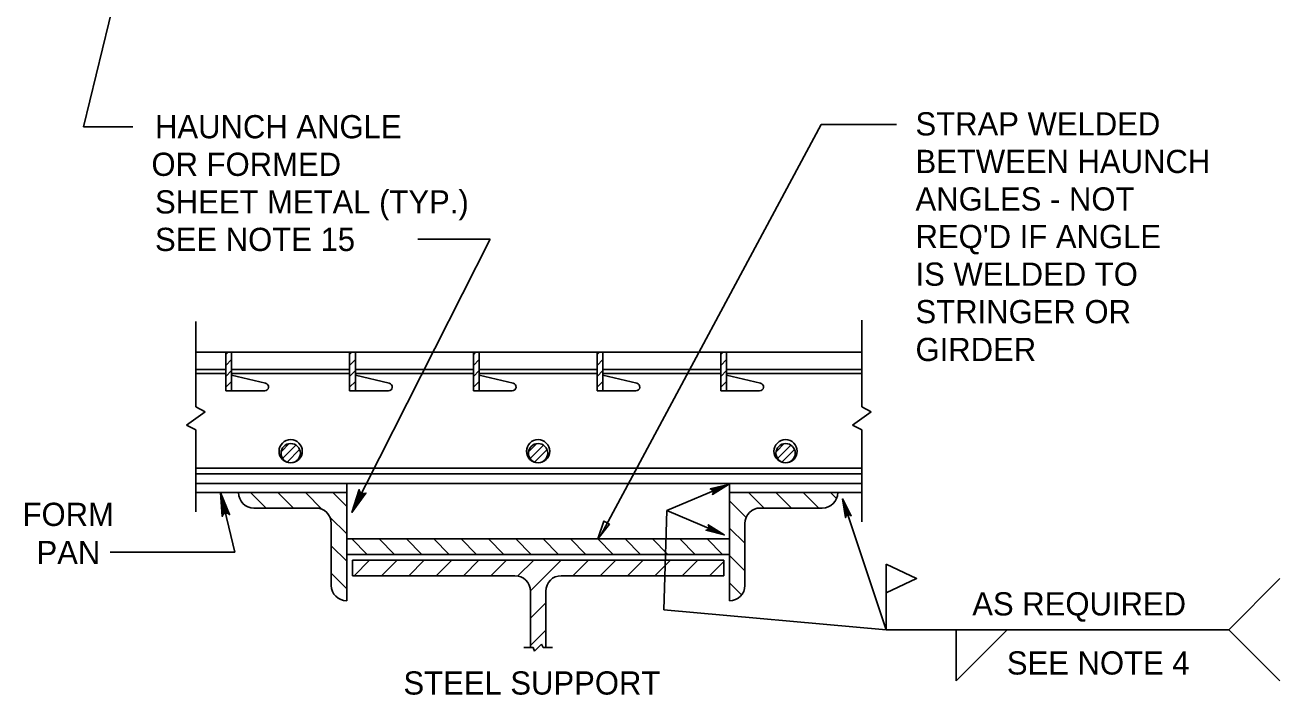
# Model space of a CAD drawing. Extents: x -24512 to -22484, y 4569 to 6351.
# Drawn here: x -23765 to -23602.7, y 5363.7 to 5450.3 of the extents above; entities that cross this region are included whole.
import ezdxf

# ---------------------------------------------------------------- set-up
doc = ezdxf.new("R2010")
doc.units = 0
for name, color, linetype in [('1', 7, 'Continuous'), ('10', 7, 'Continuous'), ('3', 7, 'Continuous'), ('4', 7, 'Continuous'), ('9', 7, 'Continuous')]:
    doc.layers.add(name, color=color, linetype=linetype)

# ---------------------------------------------------------------- blocks, each defined once
blk = doc.blocks.new('SYM012')
at = {"layer": '3'}
for p, q in [((12.764875, 6.492125), (12.825, 6.552375)), ((12.764875, 6.207), (12.916, 6.35825)), ((12.764875, 5.921875), (12.916, 6.073125)), ((12.764875, 5.63675), (12.916, 5.788))]:
    blk.add_line(p, q, dxfattribs=at)
blk = doc.blocks.new('SYM013')
at = {"layer": '3'}
for p, q in [((10.418625, 11.48775), (10.630375, 11.699625)), ((10.457, 11.312375), (10.805875, 11.66125)), ((10.574625, 11.21625), (10.902, 11.5435)), ((10.82875, 11.256375), (10.86175, 11.2895))]:
    blk.add_line(p, q, dxfattribs=at)
blk = doc.blocks.new('SYM022')
at = {"layer": '3'}
for p, q in [((104.738375, 112.667875), (104.335125, 113.071125)), ((105.451125, 112.667875), (105.048, 113.071125)), ((106.199875, 112.632), (105.76075, 113.071125)), ((106.84, 112.70475), (106.473625, 113.071125)), ((106.84, 111.991875), (106.400875, 112.431)), ((106.84, 111.279125), (106.43675, 111.68225)), ((106.84, 110.56625), (106.43675, 110.9695))]:
    blk.add_line(p, q, dxfattribs=at)
blk = doc.blocks.new('SYM023')
at = {"layer": '3'}
for p, q in [((117.103, 112.421), (116.66825, 112.85575)), ((117.568875, 112.667875), (117.16575, 113.071125)), ((118.28175, 112.667875), (117.8785, 113.071125)), ((118.9945, 112.667875), (118.591375, 113.071125)), ((119.459625, 112.915625), (119.304125, 113.071125)), ((117.0715, 111.739625), (116.66825, 112.142875)), ((117.0715, 111.026875), (116.66825, 111.430125)), ((116.98425, 110.401375), (116.66825, 110.71725))]:
    blk.add_line(p, q, dxfattribs=at)
blk = doc.blocks.new('SYM024')
at = {"layer": '3'}
for p, q in [((107.372375, 111.4595), (106.969125, 111.86275)), ((108.08525, 111.4595), (107.682, 111.86275)), ((108.798, 111.4595), (108.39475, 111.86275)), ((109.51075, 111.4595), (109.107625, 111.86275)), ((110.223625, 111.4595), (109.820375, 111.86275)), ((110.936375, 111.4595), (110.53325, 111.86275)), ((111.64925, 111.4595), (111.246, 111.86275)), ((112.362, 111.4595), (111.958875, 111.86275)), ((113.074875, 111.4595), (112.671625, 111.86275)), ((113.787625, 111.4595), (113.3845, 111.86275)), ((114.5005, 111.4595), (114.09725, 111.86275)), ((115.21325, 111.4595), (114.81, 111.86275)), ((115.926125, 111.4595), (115.522875, 111.86275)), ((116.638875, 111.4595), (116.235625, 111.86275))]:
    blk.add_line(p, q, dxfattribs=at)

msp = doc.modelspace()

# ---------------------------------------------------------------- linework, layer by layer
at = {"layer": '1'}
for p, q in [((-23722.42, 5379.15), (-23720.42, 5381.15)), ((-23718.88, 5379.15), (-23716.88, 5381.15)), ((-23715.35, 5379.15), (-23713.35, 5381.15)), ((-23711.81, 5379.15), (-23709.81, 5381.15)), ((-23708.28, 5379.15), (-23706.28, 5381.15)), ((-23704.74, 5379.15), (-23702.74, 5381.15)), ((-23701.25, 5379.11), (-23699.21, 5381.15)), ((-23699.64, 5377.19), (-23695.67, 5381.15)), ((-23694.14, 5379.15), (-23692.14, 5381.15)), ((-23690.6, 5379.15), (-23688.6, 5381.15)), ((-23687.07, 5379.15), (-23685.07, 5381.15)), ((-23683.53, 5379.15), (-23681.53, 5381.15)), ((-23680, 5379.15), (-23678, 5381.15)), ((-23676.46, 5379.15), (-23674.64, 5380.98)), ((-23699.64, 5373.65), (-23697.64, 5375.65)), ((-23699.64, 5370.12), (-23697.64, 5372.12))]:
    msp.add_line(p, q, dxfattribs=at)
at = {"layer": '10'}
for p, q in [((-23682.01, 5387.59), (-23674, 5390.95)), ((-23682.39, 5374.73), (-23682.01, 5387.59)), ((-23682.01, 5387.59), (-23674.56, 5384.42)), ((-23653.65, 5372.16), (-23682.39, 5374.73))]:
    msp.add_line(p, q, dxfattribs=at)
for points in [[(-23739.39, 5386.99), (-23739.21, 5387.15), (-23739.72, 5389.89), (-23739.39, 5386.99), (-23739.48, 5386.82), (-23739.72, 5389.89), (-23738.93, 5387.22), (-23738.7, 5387.17), (-23739.72, 5389.89), (-23738.53, 5387.05), (-23738.7, 5387.17)], [(-23721.08, 5389.76), (-23721.31, 5389.76), (-23722.71, 5387.34), (-23721.08, 5389.76), (-23720.9, 5389.83), (-23722.71, 5387.34), (-23721.58, 5389.89), (-23721.72, 5390.07), (-23722.71, 5387.34), (-23721.77, 5390.28), (-23721.72, 5390.07)], [(-23676.24, 5390.32), (-23676.1, 5390.2), (-23674, 5390.95), (-23676.24, 5390.32), (-23676.39, 5390.37), (-23674, 5390.95), (-23676.01, 5389.99), (-23676.02, 5389.8), (-23674, 5390.95), (-23676.09, 5389.65), (-23676.02, 5389.8)], [(-23658.83, 5386.8), (-23658.7, 5386.94), (-23659.28, 5389.08), (-23658.83, 5386.8), (-23658.89, 5386.66), (-23659.28, 5389.08), (-23658.48, 5387.01), (-23658.29, 5386.99), (-23659.28, 5389.08), (-23658.15, 5386.9), (-23658.29, 5386.99)], [(-23676.57, 5385.59), (-23676.56, 5385.4), (-23674.56, 5384.42), (-23676.57, 5385.59), (-23676.64, 5385.73), (-23674.56, 5384.42), (-23676.65, 5385.19), (-23676.78, 5385.07), (-23674.56, 5384.42), (-23676.94, 5385.02), (-23676.78, 5385.07)]]:
    msp.add_lwpolyline(points, dxfattribs=at)
at = {"layer": '4'}
for p, q in [((-23742.88, 5412), (-23742.88, 5400.97)), ((-23656.77, 5412.19), (-23656.77, 5400.97)), ((-23742.88, 5408.05), (-23656.77, 5408.05)), ((-23739.01, 5408.05), (-23739.01, 5403.05)), ((-23738.26, 5408.05), (-23738.26, 5403.05)), ((-23723.01, 5408.05), (-23723.01, 5403.05)), ((-23722.26, 5408.05), (-23722.26, 5403.05)), ((-23707.01, 5408.05), (-23707.01, 5403.05)), ((-23706.26, 5408.05), (-23706.26, 5403.05)), ((-23691.01, 5408.05), (-23691.01, 5403.05)), ((-23690.26, 5408.05), (-23690.26, 5403.05)), ((-23675.01, 5408.05), (-23675.01, 5403.05)), ((-23674.26, 5408.05), (-23674.26, 5403.05)), ((-23742.88, 5405.8), (-23739.01, 5405.8)), ((-23742.88, 5405.3), (-23739.01, 5405.3)), ((-23738.26, 5405.8), (-23723.01, 5405.8)), ((-23738.26, 5405.3), (-23723.01, 5405.3)), ((-23738.26, 5405.06), (-23733.88, 5404.04)), ((-23722.26, 5405.8), (-23707.01, 5405.8)), ((-23722.26, 5405.3), (-23707.01, 5405.3)), ((-23722.26, 5405.06), (-23717.88, 5404.04)), ((-23706.26, 5405.8), (-23691.01, 5405.8)), ((-23706.26, 5405.3), (-23691.01, 5405.3)), ((-23706.26, 5405.06), (-23701.88, 5404.04)), ((-23690.26, 5405.8), (-23675.01, 5405.8)), ((-23690.26, 5405.3), (-23675.01, 5405.3)), ((-23690.26, 5405.06), (-23685.88, 5404.04)), ((-23674.26, 5405.8), (-23656.77, 5405.8)), ((-23674.26, 5405.3), (-23656.77, 5405.3)), ((-23674.26, 5405.06), (-23669.88, 5404.04)), ((-23739.01, 5403.05), (-23738.26, 5403.05)), ((-23738.26, 5403.05), (-23733.99, 5403.05)), ((-23723.01, 5403.05), (-23722.26, 5403.05)), ((-23722.26, 5403.05), (-23717.99, 5403.05)), ((-23707.01, 5403.05), (-23706.26, 5403.05)), ((-23706.26, 5403.05), (-23701.99, 5403.05)), ((-23691.01, 5403.05), (-23690.26, 5403.05)), ((-23690.26, 5403.05), (-23685.99, 5403.05)), ((-23675.01, 5403.05), (-23674.26, 5403.05)), ((-23674.26, 5403.05), (-23669.99, 5403.05)), ((-23744.08, 5398.61), (-23741.67, 5400.35)), ((-23742.88, 5400.97), (-23741.67, 5400.35)), ((-23657.98, 5398.61), (-23655.57, 5400.35)), ((-23656.77, 5400.97), (-23655.57, 5400.35)), ((-23744.08, 5398.61), (-23742.88, 5397.99)), ((-23742.88, 5397.99), (-23742.88, 5387.41)), ((-23657.98, 5398.61), (-23656.77, 5397.99)), ((-23656.77, 5397.99), (-23656.77, 5386.1)), ((-23742.88, 5393.05), (-23656.77, 5393.05)), ((-23742.88, 5392.3), (-23656.77, 5392.3)), ((-23742.88, 5391.05), (-23656.77, 5391.05)), ((-23723.38, 5389.89), (-23742.88, 5389.89)), ((-23723.38, 5375.9), (-23723.38, 5391.05)), ((-23673.89, 5375.9), (-23673.89, 5391.05)), ((-23673.89, 5389.89), (-23656.77, 5389.89)), ((-23735.38, 5387.89), (-23727.38, 5387.89)), ((-23661.89, 5387.89), (-23669.89, 5387.89)), ((-23725.38, 5385.9), (-23725.38, 5377.9)), ((-23671.89, 5385.9), (-23671.89, 5377.9)), ((-23722.63, 5381.15), (-23722.63, 5379.15)), ((-23722.63, 5381.15), (-23674.64, 5381.15)), ((-23674.64, 5381.15), (-23674.64, 5379.15)), ((-23722.63, 5379.15), (-23701.64, 5379.15)), ((-23695.64, 5379.15), (-23674.64, 5379.15)), ((-23699.64, 5377.15), (-23699.64, 5369.85)), ((-23697.64, 5377.15), (-23697.64, 5369.85)), ((-23699.09, 5369.39), (-23698.18, 5370.31)), ((-23698.18, 5370.31), (-23697.99, 5369.85)), ((-23700.48, 5369.85), (-23699.29, 5369.85)), ((-23699.29, 5369.85), (-23699.09, 5369.39)), ((-23697.99, 5369.85), (-23696.79, 5369.85))]:
    msp.add_line(p, q, dxfattribs=at)
msp.add_lwpolyline([(-23723.38, 5383.9), (-23723.38, 5381.9), (-23673.89, 5381.9), (-23673.89, 5383.9)], close=True, dxfattribs=at)
for centre, radius in [((-23730.63, 5395.24), 1.5), ((-23730.63, 5394.99), 1.25), ((-23698.64, 5395.24), 1.5), ((-23698.64, 5394.99), 1.25), ((-23666.64, 5395.24), 1.5), ((-23666.64, 5394.99), 1.25)]:
    msp.add_circle(centre, radius, dxfattribs=at)
for centre, radius, start, end in [((-23733.99, 5403.55), 0.5, 270, 76.9027), ((-23717.99, 5403.55), 0.5, 270, 76.9027), ((-23701.99, 5403.55), 0.5, 270, 76.9027), ((-23685.99, 5403.55), 0.5, 270, 76.9027), ((-23669.99, 5403.55), 0.5, 270, 76.9027), ((-23735.38, 5389.89), 2, 180, 270), ((-23661.89, 5389.89), 2, 270, 0), ((-23727.38, 5385.9), 2, 0, 90), ((-23669.89, 5385.9), 2, 90, 180), ((-23701.64, 5377.15), 2, 0, 90), ((-23695.64, 5377.15), 2, 90, 180), ((-23723.38, 5377.9), 2, 180, 270), ((-23673.89, 5377.9), 2, 270, 0)]:
    msp.add_arc(centre, radius, start, end, dxfattribs=at)
at = {"layer": '9'}
for p, q in [((-23749.57, 5469.36), (-23757.41, 5437.2)), ((-23751.05, 5437.2), (-23757.41, 5437.2)), ((-23662.05, 5437.5), (-23690.52, 5384.41)), ((-23652.28, 5437.5), (-23662.05, 5437.5)), ((-23722.71, 5387.34), (-23704.82, 5422.66)), ((-23704.82, 5422.66), (-23714.19, 5422.66)), ((-23737.85, 5382.19), (-23739.72, 5389.89)), ((-23659.28, 5389.08), (-23653.65, 5372.16)), ((-23737.85, 5382.19), (-23753.95, 5382.19)), ((-23653.65, 5372.16), (-23653.65, 5380.65)), ((-23602.72, 5378.78), (-23609.34, 5372.16)), ((-23609.34, 5372.16), (-23653.65, 5372.16)), ((-23644.6, 5372.16), (-23644.6, 5365.54)), ((-23644.6, 5365.54), (-23637.98, 5372.16)), ((-23602.72, 5365.54), (-23609.34, 5372.16))]:
    msp.add_line(p, q, dxfattribs=at)
for points in [[(-23689.42, 5385.81), (-23690.12, 5386.2), (-23690.92, 5383.9)], [(-23653.65, 5380.65), (-23649.71, 5378.79), (-23653.65, 5376.93)]]:
    msp.add_lwpolyline(points, close=True, dxfattribs=at)

# ---------------------------------------------------------------- block references
at = {"layer": '3'}
for name, p, xscale, yscale in [('SYM012', (-23802.32, 5375.55), 4.9596915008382, 4.9596915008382), ('SYM012', (-23786.32, 5375.55), 4.9596915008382, 4.9596915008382), ('SYM012', (-23770.32, 5375.55), 4.9596915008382, 4.9596915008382), ('SYM012', (-23754.32, 5375.55), 4.9596915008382, 4.9596915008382), ('SYM012', (-23738.32, 5375.55), 4.9596915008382, 4.9596915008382), ('SYM013', (-23783.54, 5338.2), 4.9596915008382, 4.9596915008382), ('SYM013', (-23751.54, 5338.2), 4.9596915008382, 4.9596915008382), ('SYM013', (-23719.55, 5338.2), 4.9596915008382, 4.9596915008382), ('SYM022', (-24253.29, 4829.08), 4.95984251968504, 4.95984251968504), ('SYM023', (-24252.54, 4829.08), 4.95984251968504, 4.95984251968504), ('SYM024', (-24253.29, 4829.08), 4.95984251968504, 4.95984251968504)]:
    msp.add_blockref(name, p, dxfattribs=dict(at, xscale=xscale, yscale=yscale))

# ---------------------------------------------------------------- texts
at = {"layer": '9'}
for s, height, p in [('HAUNCH ANGLE', 2.9999, (-23748.17, 5435.7)), ('STRAP WELDED', 2.9999, (-23649.84, 5436.07)), ('OR FORMED', 3, (-23748.63, 5430.84)), ('BETWEEN HAUNCH', 2.9999, (-23649.84, 5431.21)), ('SHEET METAL (TYP.)', 2.9999, (-23748.17, 5425.98)), ('ANGLES - NOT ', 2.9999, (-23649.84, 5426.36)), ('SEE NOTE 15', 2.9999, (-23748.17, 5421.13)), ("REQ'D IF ANGLE", 2.9999, (-23649.84, 5421.5)), ('IS WELDED TO', 2.9999, (-23649.84, 5416.64)), ('STRINGER OR', 2.9999, (-23649.84, 5411.79)), ('GIRDER', 3, (-23649.84, 5406.9)), (' FORM', 3, (-23766.41, 5385.58)), ('PAN', 3, (-23763.49, 5380.64)), ('AS REQUIRED', 2.9999, (-23642.5, 5374.01)), ('SEE NOTE 4', 3, (-23638.03, 5366.37)), ('STEEL SUPPORT', 2.9999, (-23716.05, 5363.78))]:
    msp.add_text(s, height=height, dxfattribs=at).set_placement(p)

doc.saveas('drawing.dxf')
